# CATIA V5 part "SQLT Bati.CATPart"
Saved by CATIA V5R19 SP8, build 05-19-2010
Part number: SQLT Bati
Publications: "Plan.1", "Plan.2", "Plan.3", "Droite.1", "Plan.4", "Plan.5", "Plan.6", "Droite.2", "Plan.7", "Plan.8", "Droite.3", "Point.4", "Point.5"
Bounding box of the stored display mesh (mm): x -50 to 50, y 0 to 530, z 600 to 750
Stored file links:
  G:\EU_thinkMotion\CFAO_2010\MMS_groupe3\MMS_groupe3\A reprendre\fovide\fovide\SQLT Bati.CATPart
  G:\EU_thinkMotion\CFAO_2010\MMS_groupe3\MMS_groupe3\A reprendre\fovide\fovide\fovide.CATProduct
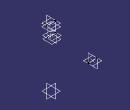
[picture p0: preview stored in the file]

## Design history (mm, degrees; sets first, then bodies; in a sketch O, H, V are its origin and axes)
Set1
  Point1 "Point.A": linked copy from another document
  Point2 "Point.O": linked copy from another document
  Point3 "Point.I": linked copy from another document
Set2 "set bati"
  Plane1: type OffsetPt, RefPlane yz-plane, RefPoint Point1
  Plane2: type OffsetPt, RefPlane xy-plane, RefPoint Point1
  Plane3: type Offset, RefPlane Plane2, Offset 40, reversed
  Line1: type Normal, RefPoint Point1, RefSkin Plane1, Start -50, End 50
  Plane4: type OffsetPt, RefPlane xy-plane, RefPoint Point2
  Plane5: type OffsetPt, RefPlane yz-plane, RefPoint Point2
  Plane6: type Offset, RefPlane Plane4, Offset 40, reversed
  Line2: type Normal, RefPoint Point2, RefSkin Plane5, Start -50, End 50
  Plane7: type OffsetPt, RefPlane yz-plane, RefPoint Point3
  Plane8: type OffsetPt, RefPlane xy-plane, RefPoint Point3
  Line3: type Normal, RefPoint Point3, RefSkin Plane7, Start -50, End 50
  Point4: type OnCurve, Support Line1, RefPoint Point1, Length 30
  Point5: type OnCurve, Support Line2, Length 20
Body1 (main body)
